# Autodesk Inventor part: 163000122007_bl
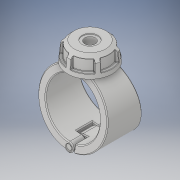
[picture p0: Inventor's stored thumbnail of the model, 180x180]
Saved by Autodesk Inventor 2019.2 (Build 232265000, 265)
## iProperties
Created: 2022-02
Part Number: 163000122007_bl
Material: Generic
Description: Plassadle Threaded 122x3/4''
Document SubType Name: Modeling
Designer: comp2
Density: 1 g/cm^3
Appearance: Default
Author: comp2
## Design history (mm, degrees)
derived "16300.ipt"
feature "Solid1::16300.ipt" dims "ScaleForDerivedMember" = 10
feature "Solid2::16300.ipt" dims "ScaleForDerivedMember" = 10
feature "Solid3::16300.ipt" dims "ScaleForDerivedMember" = 10
feature "Solid4::16300.ipt" dims "ScaleForDerivedMember" = 10
tag "TaggingFeature1"
body "Solid1"
body "Solid2"
body "Solid3"
body "Solid4"
other parameters: "d0" = 122 [user parameter], "d2" = 157 [user parameter], "d3" = 61 [user parameter], "d7" = 149.15 [user parameter], "d8" = 85 deg [user parameter], "d9" = 45 deg [user parameter], "d10" = 102 [user parameter], "d11" = 49 [user parameter], "d12" = 29.2495 [user parameter], "d13" = 42.84 [user parameter], "d14" = 36.1755 [user parameter], "d42" = 3.5 [user parameter], "d49" = 3.14 [user parameter], "d51" = 0 [user parameter], "d52" = 24.5 [user parameter], "d53" = 86.35 [user parameter], "d54" = 35 [user parameter], "d55" = 0 [user parameter], "d59" = 0 [user parameter], "d61" = 0 [user parameter], "d62" = 35 [user parameter], "d63" = 0 [user parameter], "d65" = 0 [user parameter], "d67" = 0 [user parameter], "d69" = 0 [user parameter], "d70" = 1 [user parameter], "d71" = 96 [user parameter], "d72" = 0 [user parameter], "d73" = 2 [user parameter], "d78" = 86.7 [user parameter], "d79" = 5.1 [user parameter], "d80" = 60 deg [user parameter], "d81" = 5.1 [user parameter], "d84" = 0 [user parameter], "d85" = 1 [user parameter], "d87" = 360 deg [user parameter], "d122" = 52 [user parameter], "d124" = 42.80128 [user parameter], "d125" = 2.08925 [user parameter], "d127" = 198 [user parameter], "d129" = 24.117 [user parameter], "d130" = 20.49945 [user parameter], "d131" = 33.8 [user parameter], "d132" = 45 deg [user parameter], "d133" = 23.66 [user parameter], "d134" = 12.0585 [user parameter], "d136" = 0 [user parameter], "d138" = 0 [user parameter], "d" = 122 [user parameter], "d1" = 25 [user parameter], "B" = 157 [user parameter], "E_" = 54 [user parameter], "E1" = 102 [user parameter], "H1" = 198 [user parameter], "H2" = 52 [user parameter], "H3" = 78 [user parameter], "H_costum" = 49 [user parameter], "Rp" = 24.117 [user parameter], "d128" = 41.785 [user parameter]
